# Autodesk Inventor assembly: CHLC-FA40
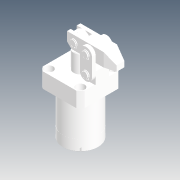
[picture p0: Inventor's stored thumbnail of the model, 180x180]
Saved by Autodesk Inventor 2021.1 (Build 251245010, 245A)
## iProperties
Company: Microsoft
Created: 2019-11
Part Number: CHLC-FA40
Description: STEP AP214
Document SubType Name: Assembly
Designer: user
Title: CHLC-FA40.STEP
Author: Windows
Revision Number: ÈÎºÎ
Sending System: SolidWorks 2015
Preprocessor: SwSTEP 2.0
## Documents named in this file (10)
- D:\Vault_2016\Projekty\Clamptek\Hydraulic\CHLC\CHLC-40\Inventor\CHLC-FA40\CHLC-FA40.iam
- D:\Vault_2016\Projekty\Clamptek\Hydraulic\CHLC\CHLC-40\Inventor\CHLC-FA40\CHLC-FA40-05.ipt
- D:\Vault_2016\Projekty\Clamptek\Hydraulic\CHLC\CHLC-40\Inventor\CHLC-FA40\CHLC-FA40-06.ipt
- D:\Vault_2016\Projekty\Clamptek\Hydraulic\CHLC\CHLC-40\Inventor\CHLC-FA40\CHLC-40-08.ipt
- D:\Vault_2016\Projekty\Clamptek\Hydraulic\CHLC\CHLC-40\Inventor\CHLC-FA40\CHLC-40-01.ipt
- D:\Vault_2016\Projekty\Clamptek\Hydraulic\CHLC\CHLC-40\Inventor\CHLC-FA40\CHLC-40-03.ipt
- D:\Vault_2016\Projekty\Clamptek\Hydraulic\CHLC\CHLC-40\Inventor\CHLC-FA40\CHLC-40-02.ipt
- D:\Vault_2016\Projekty\Clamptek\Hydraulic\CHLC\CHLC-40\Inventor\CHLC-FA40\CHLC-40-04.ipt
- D:\Vault_2016\Projekty\Clamptek\Hydraulic\CHLC\CHLC-40\Inventor\CHLC-FA40\CHLC-40-06.ipt
- D:\Vault_2016\Projekty\Clamptek\Hydraulic\CHLC\CHLC-40\Inventor\CHLC-FA40\M6LC.ipt
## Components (19 placed, 19 different names)
1. CHLC-FA40-05_1
2. CHLC-FA40-06_2
3. CHLC-40-08_3
4. CHLC-40-01_4
5. CHLC-40-03_5
6. CHLC-40-03_6
7. CHLC-40-02_7
8. CHLC-40-02_8
9. CHLC-40-04_9
10. CHLC-40-06_10
11. CHLC-40-06_11
12. CHLC-40-06_12
13. CHLC-40-06_13
14. CHLC-40-06_14
15. CHLC-40-06_15
16. M6LC_16
17. M6LC_17
18. M6LC_18
19. M6LC_19
